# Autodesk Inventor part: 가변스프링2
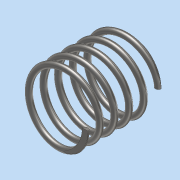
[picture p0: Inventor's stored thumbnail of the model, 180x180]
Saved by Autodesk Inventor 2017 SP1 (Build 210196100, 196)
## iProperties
Part Number: 가변스프링2
Material: 강철, 연강
Document SubType Name: Modeling
Designer: MRC
Density: 7.85 g/cm^3
Appearance: 반연마
Mass: 8.38159 g
Surface Area: 21.6559 cm^2
Volume: 1.06772 cm^3
Author: MRC
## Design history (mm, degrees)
sketch "스케치1"
  geometry: L1 (0, 0)-(0, 25.358); L2 (0, 0)-(11, 0); L3 (0, 25.358)-(11, 25.358); C1 r 1 at (11, 0)
  constraints: 6 end point, 2 horizontal, 1 centre point, 1 coincident, 1 vertical
  dimensions: "d0" = 25.35829 distance of L1.start L1.end (derived); "d1" = 2 diameter of C1; "d2" = 22 diameter of L2.end L1
feature "코일1" sketch "스케치1" pitch "d3" = 10; turns "d5" = 5; dims "d4" = 25.35829 (= d0), "d6" = 0, angle "d7" = 90 deg, angle "d8" = 90 deg, "d9" = 0, "d10" = 0
sketch "스케치2"
  geometry: L1 (15, 0)-(-15, 0); L2 (-15, 0)-(-15, 25.358); L3 (-15, 25.358)-(15, 25.358); L4 (15, 25.358)-(15, 0); 1 further point
  constraints: 8 end point, 2 parallel, 1 horizontal, 1 midpoint, 1 perpendicular
  dimensions: "d11" = 25.35829 distance of L3.end L1.start (= d0); "d12" = 30 distance between parallel lines of L2 L4; "d13" = 15 distance from line of point (0, 0) L4 (= 0.5 x d12)
extrude "돌출1" sketch "스케치2" stored distance "d14" = 30; taper "d15" = 0 deg
node "솔리드1"
